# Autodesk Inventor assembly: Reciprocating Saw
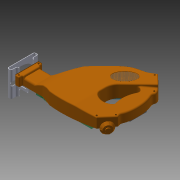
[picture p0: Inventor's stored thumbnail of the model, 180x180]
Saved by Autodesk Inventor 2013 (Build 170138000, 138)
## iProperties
Created: 2008-06
Part Number: Reciprocating Saw
Document SubType Name: Assembly
Designer: tangg
Mass: 711.371 g
Surface Area: 3987.93 cm^2
Volume: 242.811 cm^3
Density: 2.92973 g/cm^3
Author: tangg
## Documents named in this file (11)
- C:\Users\boganb\Documents\B2 Design\Goodyear\2013 Tutorial Files\Dynamic Simulation 1 and 2\Reciprocating Saw.iam
- C:\Users\boganb\Documents\B2 Design\Goodyear\2013 Tutorial Files\Dynamic Simulation 1 and 2\Saw layout.ipt
- C:\Users\boganb\Documents\B2 Design\Goodyear\2013 Tutorial Files\Dynamic Simulation 1 and 2\Guide.ipt
- C:\Users\boganb\Documents\B2 Design\Goodyear\2013 Tutorial Files\Dynamic Simulation 1 and 2\Motor housing.ipt
- C:\Users\boganb\Documents\B2 Design\Goodyear\2013 Tutorial Files\Dynamic Simulation 1 and 2\Case.ipt
- C:\Users\boganb\Documents\B2 Design\Goodyear\2013 Tutorial Files\Dynamic Simulation 1 and 2\Follower.ipt
- C:\Users\boganb\Documents\B2 Design\Goodyear\2013 Tutorial Files\Dynamic Simulation 1 and 2\Fence.ipt
- C:\Users\boganb\Documents\B2 Design\Goodyear\2013 Tutorial Files\Dynamic Simulation 1 and 2\Cam crank.iam
- C:\Users\boganb\Documents\B2 Design\Goodyear\2013 Tutorial Files\Dynamic Simulation 1 and 2\Motor.iam
- C:\Users\boganb\Documents\B2 Design\Goodyear\2013 Tutorial Files\Dynamic Simulation 1 and 2\Follower Roller.ipt
- C:\Users\boganb\Documents\B2 Design\Goodyear\2013 Tutorial Files\Dynamic Simulation 1 and 2\SKFRLS 4 A-2ZANSI.ipt
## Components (11 placed, 10 different names)
1. Saw layout:1 — Flush:15, Mate:66, Mate:76, Mate:77
2. Case:1 — Flush:16, Mate:74, Flush:19, Flush:20
3. Fence:1 — Flush:16, Mate:74
4. Guide:1 — Flush:15, Mate:71, Mate:72
5. SKF Series RLS- with Two Shields RLS 4 A-2Z:1 — Flush:19
6. SKF Series RLS- with Two Shields RLS 4 A-2Z:2 — Flush:20
7. Motor housing:1 — Mate:66, Mate:73
8. Cam crank:1 [sub-assembly] — Mate:76, Mate:77
9. Motor:1 [sub-assembly] — Mate:73
10. Follower:1 — Mate:71, Mate:72, Mate:75, Flush:17
11. Follower Roller:1 — Mate:75, Flush:17
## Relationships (13: Mate 8, Flush 5)
- Flush:15: Saw layout:1 ↔ Guide:1
- Flush:16: Case:1 ↔ Fence:1
- Mate:66: Saw layout:1 ↔ Motor housing:1
- Mate:71: Guide:1 ↔ Follower:1
- Mate:72: Guide:1 ↔ Follower:1
- Mate:73: Motor housing:1 ↔ Motor:1
- Mate:74: Case:1 ↔ Fence:1
- Mate:75: Follower:1 ↔ Follower Roller:1
- Flush:17: Follower:1 ↔ Follower Roller:1
- Mate:76: Saw layout:1 ↔ Cam crank:1
- Mate:77: Saw layout:1 ↔ Cam crank:1
- Flush:19: Case:1 ↔ SKF Series RLS- with Two Shields RLS 4 A-2Z:1
- Flush:20: Case:1 ↔ SKF Series RLS- with Two Shields RLS 4 A-2Z:2
